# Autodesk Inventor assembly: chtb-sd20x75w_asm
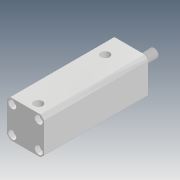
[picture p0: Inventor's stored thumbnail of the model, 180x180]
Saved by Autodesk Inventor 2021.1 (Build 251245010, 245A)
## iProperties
Company: Microsoft
Created: 2018-05
Part Number: chtb-sd20x75w_asm
Description: STEP AP214
Document SubType Name: Assembly
Designer: user
Title: chtb-sd20x75w_asm.STEP
Author: Windows
Revision Number: ÈÎºÎ
Sending System: SolidWorks 2015
Preprocessor: SwSTEP 2.0
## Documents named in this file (4)
- D:\Vault_2016\Projekty\Clamptek\Hydraulic\CHTB\CHTB-20\Inventor\CHTB-SD20x75W\chtb-sd20x75w_asm.iam
- D:\Vault_2016\Projekty\Clamptek\Hydraulic\CHTB\CHTB-20\Inventor\CHTB-SD20x75W\CHTB-SD20X75NBT.ipt
- D:\Vault_2016\Projekty\Clamptek\Hydraulic\CHTB\CHTB-20\Inventor\CHTB-SD20x75W\CHTB-SD20X75WHSG.ipt
- D:\Vault_2016\Projekty\Clamptek\Hydraulic\CHTB\CHTB-20\Inventor\CHTB-SD20x75W\QG.ipt
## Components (3 placed, 3 different names)
1. CHTB-SD20X75NBT_1
2. CHTB-SD20X75WHSG_2
3. QG_3
